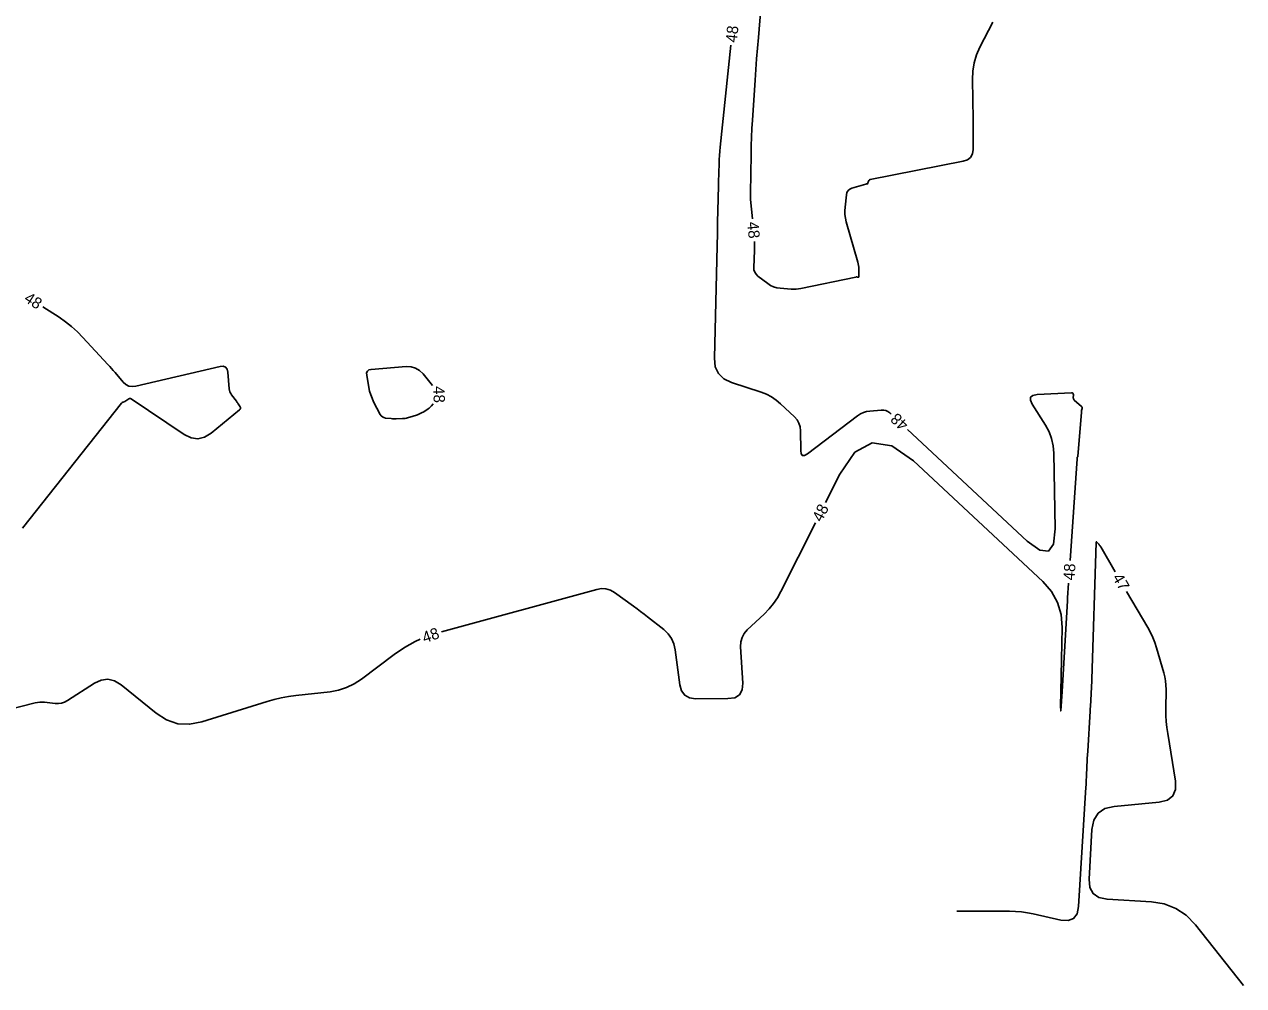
# Model space of a CAD drawing. Extents: x 2384780 to 2405861, y 547869 to 573706.
# Drawn here: x 2393690.5 to 2393906.5, y 552178.5 to 552348.9 of the extents above; entities that cross this region are included whole.
import ezdxf

# ---------------------------------------------------------------- set-up
doc = ezdxf.new("R2010")
doc.units = 0
doc.layers.add('Old_Level_60', color=7, linetype='Continuous')

msp = doc.modelspace()

# ---------------------------------------------------------------- linework, layer by layer
at = {"layer": 'Old_Level_60'}
for points in [[(2393821.27625, 552355.39675), (2393820.5465, 552346.5765), (2393820.394, 552344.686), (2393820.24875, 552342.79525), (2393820.11125, 552340.90375), (2393819.9815, 552339.01175), (2393819.50825, 552331.916), (2393819.417, 552330.396), (2393819.34625, 552328.875), (2393819.29575, 552327.35325), (2393819.2655, 552325.83075), (2393819.175, 552318.942), (2393819.17275, 552318.83275), (2393819.169, 552318.72375), (2393819.1635, 552318.61475), (2393819.15675, 552318.50575), (2393819.1315, 552318.14975), (2393819.128, 552318.0735), (2393819.1275, 552317.99725), (2393819.1305, 552317.92125), (2393819.13675, 552317.845), (2393819.49975, 552314.3925)], [(2393820.46, 552304.263), (2393822.21475, 552302.91975), (2393822.71425, 552302.58975), (2393823.245, 552302.34125), (2393823.8065, 552302.174), (2393824.399, 552302.088), (2393826.38525, 552301.94025), (2393826.80975, 552301.9235), (2393827.2325, 552301.93625), (2393827.65325, 552301.979), (2393828.072, 552302.05125), (2393837.84, 552304.0885), (2393837.8985, 552304.098), (2393837.957, 552304.10175), (2393838.0155, 552304.09975), (2393838.07425, 552304.09225), (2393838.26625, 552304.05875), (2393838.30225, 552304.05775), (2393838.328, 552304.069), (2393838.3435, 552304.09225), (2393838.34875, 552304.128), (2393838.349, 552305.5305), (2393838.33875, 552305.8295), (2393838.308, 552306.12575), (2393838.2565, 552306.419), (2393838.18425, 552306.7095), (2393836.13475, 552313.90075), (2393835.98475, 552314.54), (2393835.8975, 552315.18475), (2393835.87325, 552315.835), (2393835.912, 552316.4905), (2393836.14075, 552318.64075), (2393836.23925, 552319.06075), (2393836.43625, 552319.39875), (2393836.73175, 552319.65525), (2393837.126, 552319.83), (2393839.5935, 552320.5745), (2393839.628, 552320.58325), (2393839.663, 552320.58875), (2393839.69825, 552320.591), (2393839.73375, 552320.58975), (2393839.85075, 552320.581), (2393839.87375, 552320.58225), (2393839.89225, 552320.59025), (2393839.9065, 552320.6045), (2393839.91625, 552320.62525), (2393840.06925, 552321.10775), (2393840.1115, 552321.20075), (2393840.17175, 552321.27325), (2393840.25075, 552321.325), (2393840.348, 552321.35625), (2393856.85425, 552324.59975), (2393857.60725, 552324.857), (2393858.148, 552325.29075), (2393858.47675, 552325.90125), (2393858.59325, 552326.68825), (2393858.62725, 552329.548), (2393858.632, 552330.16075), (2393858.632, 552330.7735), (2393858.62725, 552331.38625), (2393858.6175, 552331.999), (2393858.4775, 552339.104), (2393858.53875, 552340.604), (2393858.782, 552342.06175), (2393859.20775, 552343.477), (2393859.81575, 552344.84975), (2393862.09925, 552349.265)], [(2393815.6805, 552345.2015), (2393813.79275, 552327.1205), (2393813.72325, 552326.38925), (2393813.667, 552325.657), (2393813.62425, 552324.92375), (2393813.595, 552324.18975), (2393813.4935, 552320.87825), (2393813.49175, 552320.82025), (2393813.48975, 552320.76225), (2393813.488, 552320.7045), (2393813.48625, 552320.6465), (2393813.4805, 552320.45725), (2393813.47925, 552320.4165), (2393813.47825, 552320.376), (2393813.477, 552320.3355), (2393813.476, 552320.29475), (2393813.36225, 552315.77075), (2393813.34775, 552315.1605), (2393813.33525, 552314.55025), (2393813.32425, 552313.94), (2393813.315, 552313.32975), (2393813.28775, 552311.336), (2393813.28125, 552310.90875), (2393813.2735, 552310.48175), (2393813.26475, 552310.0545), (2393813.2545, 552309.62725), (2393812.752, 552289.6805), (2393812.90975, 552288.1915), (2393813.46525, 552286.9835), (2393814.4185, 552286.0565), (2393815.7695, 552285.4105), (2393821.0345, 552283.69375), (2393821.989, 552283.32375), (2393822.8845, 552282.85525), (2393823.7215, 552282.28875), (2393824.49975, 552281.6235), (2393826.94575, 552279.2905), (2393827.40525, 552278.7625), (2393827.73575, 552278.1785), (2393827.93725, 552277.53825), (2393828.0095, 552276.842), (2393828.047, 552273.3265), (2393828.129, 552272.7245), (2393828.3585, 552272.425), (2393828.736, 552272.428), (2393829.26125, 552272.7335), (2393838.12025, 552279.4885), (2393838.62575, 552279.82175), (2393839.162, 552280.07475), (2393839.7295, 552280.247), (2393840.32775, 552280.339), (2393842.33325, 552280.508), (2393842.74875, 552280.503), (2393843.13575, 552280.41525), (2393843.494, 552280.24525), (2393843.82375, 552279.9925), (2393844.05775, 552279.7745)], [(2393819.85075, 552310.409), (2393819.86375, 552309.653), (2393819.8485, 552308.804), (2393819.74175, 552305.78525), (2393819.774, 552305.335), (2393819.9045, 552304.9315), (2393820.13325, 552304.574), (2393820.46, 552304.263)], [(2393690.1715, 552259.5575), (2393707.71675, 552281.715), (2393707.77675, 552281.78225), (2393707.8435, 552281.84075), (2393707.91675, 552281.89025), (2393707.997, 552281.93125), (2393708.2695, 552282.051), (2393708.3275, 552282.07775), (2393708.3845, 552282.10625), (2393708.44025, 552282.13675), (2393708.49525, 552282.16925), (2393709.004, 552282.4815), (2393709.1125, 552282.531), (2393709.2205, 552282.54625), (2393709.32775, 552282.52675), (2393709.43425, 552282.47275), (2393718.83225, 552276.16875), (2393720.0525, 552275.564), (2393721.25125, 552275.4005), (2393722.42875, 552275.6785), (2393723.585, 552276.398), (2393728.63675, 552280.54425), (2393728.7525, 552280.66975), (2393728.805, 552280.80475), (2393728.79425, 552280.94925), (2393728.7205, 552281.10325), (2393728.37625, 552281.62175), (2393728.30175, 552281.73225), (2393728.2255, 552281.84175), (2393728.148, 552281.95025), (2393728.06875, 552282.0575), (2393727.21475, 552283.19725), (2393727.05125, 552283.449), (2393726.9265, 552283.71575), (2393726.84075, 552283.99725), (2393726.794, 552284.29375), (2393726.5275, 552287.24925), (2393726.40025, 552287.78525), (2393726.13225, 552288.127), (2393725.724, 552288.27425), (2393725.175, 552288.227), (2393710.24175, 552284.74575), (2393709.60275, 552284.6745), (2393709.01875, 552284.77175), (2393708.48975, 552285.0375), (2393708.0155, 552285.47175), (2393706.55625, 552287.16525), (2393706.24225, 552287.52675), (2393705.92525, 552287.88575), (2393705.60525, 552288.24225), (2393705.28225, 552288.596), (2393700.86975, 552293.391), (2393699.89575, 552294.38475), (2393698.86525, 552295.3115), (2393697.778, 552296.17125), (2393696.63425, 552296.96375), (2393693.7685, 552298.819)], [(2393762.835, 552284.8525), (2393761.14475, 552286.9235), (2393760.518, 552287.541), (2393759.80725, 552287.96125), (2393759.012, 552288.1845), (2393758.13275, 552288.21025), (2393751.9325, 552287.7205), (2393751.52875, 552287.6295), (2393751.2635, 552287.43075), (2393751.137, 552287.12475), (2393751.14875, 552286.711)], [(2393751.14875, 552286.711), (2393751.5265, 552284.52975), (2393751.66675, 552283.87025), (2393751.85625, 552283.22725), (2393752.0945, 552282.601), (2393752.382, 552281.991), (2393753.5555, 552279.7285), (2393753.723, 552279.4775), (2393753.93275, 552279.2885), (2393754.18475, 552279.1615), (2393754.47925, 552279.09625), (2393755.5105, 552278.9845), (2393755.7315, 552278.9645), (2393755.953, 552278.95225), (2393756.17475, 552278.9475), (2393756.39675, 552278.95075), (2393757.48525, 552278.98475), (2393757.71725, 552278.999), (2393757.9475, 552279.027), (2393758.1755, 552279.06875), (2393758.40125, 552279.1245), (2393759.38825, 552279.39925), (2393759.5815, 552279.45675), (2393759.7725, 552279.521), (2393759.961, 552279.59175), (2393760.14725, 552279.66925), (2393760.75175, 552279.93325), (2393760.87975, 552279.9925), (2393761.005, 552280.057), (2393761.1275, 552280.127), (2393761.24675, 552280.202), (2393762.043, 552280.72725), (2393762.2085, 552280.8455), (2393762.364, 552280.97475), (2393762.50925, 552281.11525), (2393762.64475, 552281.26725), (2393762.908, 552281.58525)], [(2393846.98475, 552277.04825), (2393868.19725, 552257.2885), (2393870.39675, 552255.66375), (2393871.9515, 552255.48775), (2393872.8615, 552256.7605), (2393873.12675, 552259.482), (2393872.905, 552272.872), (2393872.7955, 552274.1915), (2393872.51175, 552275.459), (2393872.05375, 552276.6745), (2393871.42125, 552277.83775), (2393869.0705, 552281.553), (2393868.74725, 552282.2555), (2393868.78525, 552282.77125), (2393869.1845, 552283.09975), (2393869.94475, 552283.2415), (2393876.02975, 552283.55275), (2393876.177, 552283.53925), (2393876.2815, 552283.48125), (2393876.34375, 552283.379), (2393876.36325, 552283.2325), (2393876.35775, 552282.6815), (2393876.36775, 552282.5685), (2393876.4, 552282.46525), (2393876.4545, 552282.37175), (2393876.5315, 552282.28825), (2393877.81375, 552281.14275), (2393877.88225, 552281.065), (2393877.92375, 552280.979), (2393877.93775, 552280.8845), (2393877.9245, 552280.78175), (2393877.83725, 552280.43225), (2393877.82, 552280.35725), (2393877.806, 552280.2815), (2393877.795, 552280.2055), (2393877.78725, 552280.12875), (2393877.14725, 552272.271), (2393877.1445, 552272.254), (2393877.139, 552272.23825), (2393877.13075, 552272.2235), (2393877.11975, 552272.21025), (2393877.0795, 552272.1685), (2393877.072, 552272.15925), (2393877.0665, 552272.149), (2393877.063, 552272.13775), (2393877.06175, 552272.12575), (2393877.0585, 552271.99925), (2393877.05775, 552271.972), (2393877.0565, 552271.94475), (2393877.05525, 552271.91775), (2393877.0535, 552271.89075), (2393875.798, 552253.83775)], [(2393875.52025, 552249.8475), (2393875.336, 552247.19525), (2393875.3325, 552247.1445), (2393875.32975, 552247.0935), (2393875.3275, 552247.0425), (2393875.3255, 552246.9915), (2393875.32025, 552246.825), (2393875.319, 552246.7895), (2393875.31775, 552246.75375), (2393875.316, 552246.718), (2393875.314, 552246.6825), (2393874.37975, 552230.61725), (2393874.214, 552228.03575), (2393874.11725, 552227.177), (2393874.08925, 552228.04075), (2393874.1305, 552230.62725), (2393874.37875, 552241.94025), (2393874.20375, 552244.2685), (2393873.5725, 552246.40425), (2393872.485, 552248.348), (2393870.941, 552250.09925), (2393848.0245, 552271.50675), (2393844.1765, 552274.1935), (2393840.7195, 552274.69925), (2393837.65325, 552273.02425), (2393834.97775, 552269.16825), (2393832.441, 552264.10825)], [(2393830.64825, 552260.5325), (2393824.53425, 552248.33775), (2393823.926, 552247.244), (2393823.23025, 552246.21525), (2393822.44725, 552245.2515), (2393821.57675, 552244.35225), (2393818.59025, 552241.5215), (2393818.0365, 552240.8805), (2393817.65525, 552240.17125), (2393817.44625, 552239.3935), (2393817.40975, 552238.5475), (2393817.77275, 552232.108), (2393817.668, 552230.9005), (2393817.19825, 552230.038), (2393816.36375, 552229.5205), (2393815.164, 552229.348), (2393809.41975, 552229.34725), (2393808.323, 552229.4995), (2393807.49425, 552229.95725), (2393806.93375, 552230.72025), (2393806.64125, 552231.78825), (2393805.83625, 552237.99475), (2393805.60075, 552239.04975), (2393805.18175, 552240.0005), (2393804.579, 552240.84675), (2393803.79275, 552241.5885), (2393800.92425, 552243.84125), (2393800.307, 552244.32075), (2393799.68525, 552244.79425), (2393799.059, 552245.26125), (2393798.42775, 552245.72225), (2393795.061, 552248.1545), (2393794.3225, 552248.58125), (2393793.54975, 552248.819), (2393792.74275, 552248.8675), (2393791.9015, 552248.727), (2393764.4, 552241.1955)], [(2393883.78725, 552251.8255), (2393881.20625, 552256.24525), (2393881.1285, 552256.372), (2393881.0455, 552256.495), (2393880.957, 552256.6145), (2393880.8635, 552256.73), (2393880.54875, 552257.1015), (2393880.4895, 552257.15825), (2393880.446, 552257.16875), (2393880.41875, 552257.1335), (2393880.4075, 552257.05225), (2393879.64275, 552232.7965), (2393879.623, 552232.235), (2393879.59975, 552231.67375), (2393879.57275, 552231.11275), (2393879.542, 552230.55175), (2393879.4355, 552228.71975), (2393879.4125, 552228.327), (2393879.38925, 552227.9345), (2393879.366, 552227.542), (2393879.34225, 552227.1495), (2393878.91075, 552220.02875), (2393878.8735, 552219.396), (2393878.8385, 552218.763), (2393878.8055, 552218.13025), (2393878.7745, 552217.497), (2393878.677, 552215.42875), (2393878.65525, 552214.9855), (2393878.63225, 552214.5425), (2393878.60775, 552214.0995), (2393878.58175, 552213.6565), (2393877.30325, 552192.483), (2393877.03625, 552191.18925), (2393876.419, 552190.36075), (2393875.45175, 552189.99775), (2393874.1345, 552190.1), (2393869.26025, 552191.19475), (2393868.21225, 552191.39975), (2393867.158, 552191.5465), (2393866.09725, 552191.63425), (2393865.03, 552191.6635), (2393855.735, 552191.66225)], [(2393906.53375, 552178.48), (2393897.9875, 552189.278), (2393896.38025, 552190.947), (2393894.54575, 552192.1795), (2393892.484, 552192.976), (2393890.195, 552193.336), (2393882.3465, 552193.79925), (2393880.8865, 552194.09625), (2393879.87, 552194.789), (2393879.297, 552195.87775), (2393879.16775, 552197.362), (2393879.6495, 552206.1335), (2393879.974, 552207.80075), (2393880.74125, 552209.04325), (2393881.951, 552209.861), (2393883.6035, 552210.25425), (2393891.5805, 552211.0235), (2393893.04175, 552211.37975), (2393894.007, 552212.11825), (2393894.476, 552213.23975), (2393894.449, 552214.7435), (2393893.0825, 552223.165), (2393892.93225, 552224.233), (2393892.8275, 552225.3045), (2393892.7685, 552226.37925), (2393892.755, 552227.4575), (2393892.7855, 552230.98575), (2393892.76475, 552231.73825), (2393892.68975, 552232.483), (2393892.5605, 552233.22025), (2393892.37675, 552233.95), (2393891.09575, 552238.36025), (2393890.7935, 552239.2935), (2393890.43575, 552240.20275), (2393890.0225, 552241.08825), (2393889.554, 552241.95), (2393885.80425, 552248.37125)], [(2393760.62975, 552239.8745), (2393759.759, 552239.49675), (2393757.8455, 552238.43775), (2393756.025, 552237.19025), (2393750.2295, 552232.807), (2393748.94925, 552231.96325), (2393747.59275, 552231.31125), (2393746.16, 552230.8505), (2393744.65075, 552230.581), (2393738.5935, 552229.901), (2393737.30175, 552229.725), (2393736.023, 552229.488), (2393734.75675, 552229.19025), (2393733.5035, 552228.83175), (2393721.93475, 552225.22375), (2393719.7535, 552224.7985), (2393717.67625, 552224.91575), (2393715.70325, 552225.576), (2393713.83425, 552226.77875), (2393707.63225, 552231.81075), (2393706.48225, 552232.51975), (2393705.30875, 552232.7995), (2393704.11125, 552232.6505), (2393702.89025, 552232.07275), (2393698.13, 552229.013), (2393697.622, 552228.7415), (2393697.0915, 552228.566), (2393696.5385, 552228.48625), (2393695.96275, 552228.502), (2393694.045, 552228.71075), (2393693.6355, 552228.73725), (2393693.22825, 552228.7275), (2393692.8235, 552228.68125), (2393692.4215, 552228.59875), (2393684.70475, 552226.66275)]]:
    msp.add_lwpolyline(points, dxfattribs=at)

# ---------------------------------------------------------------- texts
for s, rotation, p in [('48', 84.0393917, (2393816.72675, 552345.591)), ('48', 275.0358, (2393818.58075, 552313.81375)), ('48', 327.1932222, (2393690.284, 552299.88025)), ('48', 271.2808083, (2393762.95425, 552284.73225)), ('48', 137.0307083, (2393847.30325, 552278.11825)), ('48', 63.3725833, (2393831.7645, 552260.528)), ('48', 86.0215417, (2393876.5525, 552250.273)), ('47', 300.2829861, (2393883.2095, 552250.8315)), ('48', 19.3111472, (2393761.40175, 552239.1615))]:
    msp.add_text(s, height=2, rotation=rotation, dxfattribs=at).set_placement(p)

doc.saveas('drawing.dxf')
